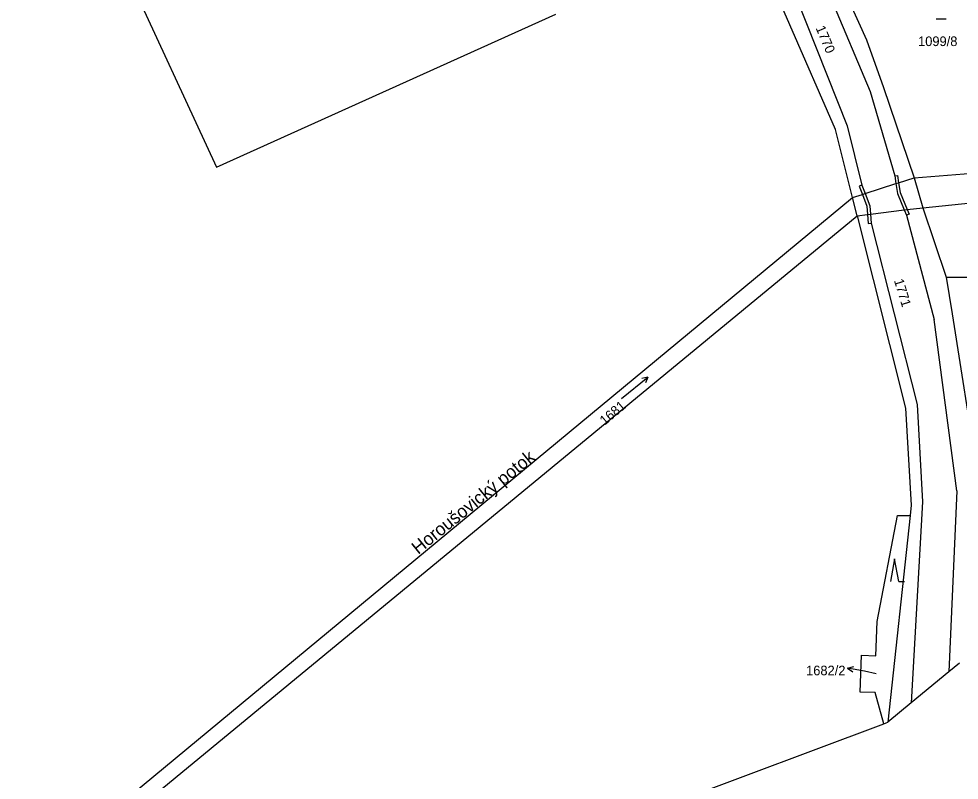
# Model space of a CAD drawing. Extents: x -724107 to -720612, y -1045267 to -1038441.
# Drawn here: x -722136.9 to -721970.9, y -1044488.4 to -1044354 of the extents above; entities that cross this region are included whole.
import ezdxf

# ---------------------------------------------------------------- set-up
doc = ezdxf.new("R2010")
doc.units = 0
for name, color, linetype in [('Hranice kat_území', 7, 'Continuous'), ('Hranice parcel', 7, 'Continuous'), ('Parcelní čísla', 7, 'Continuous'), ('Pop  PČ popisy', 7, 'Continuous'), ('Vnitřní kresba', 7, 'Continuous'), ('Značky kultur', 7, 'Continuous')]:
    doc.layers.add(name, color=color, linetype=linetype)

msp = doc.modelspace()

# ---------------------------------------------------------------- linework, layer by layer
at = {"layer": 'Hranice kat_území'}
for p, q in [((-722037.47, -1044498.36), (-721984.24, -1044478.41)), ((-721984.24, -1044478.41), (-721983.81, -1044478.25)), ((-721983.81, -1044478.25), (-721983.52, -1044478.14))]:
    msp.add_line(p, q, dxfattribs=at)
msp.add_lwpolyline([(-721970.87, -1044467.72), (-721972.74, -1044469.26), (-721979.36, -1044474.72), (-721983.52, -1044478.14)], dxfattribs=at)
at = {"layer": 'Hranice parcel'}
for p, q in [((-721978.83, -1044382.04), (-721952.21, -1044380)), ((-721978.83, -1044382.04), (-721977.33, -1044387.33)), ((-721977.33, -1044387.33), (-721924.74, -1044381.95)), ((-721988.93, -1044388.75), (-721989.74, -1044385.55)), ((-721977.33, -1044387.33), (-721973.2, -1044399.62)), ((-721973.2, -1044399.62), (-721957.88, -1044399.48)), ((-721979.56, -1044441.69), (-721983.52, -1044478.14))]:
    msp.add_line(p, q, dxfattribs=at)
for points in [[(-721998.33, -1044333.24), (-721987.3, -1044357.71), (-721984.26, -1044366.09), (-721978.83, -1044382.04)], [(-721989.74, -1044385.55), (-721992.77, -1044373.53), (-722008.86, -1044336.5)], [(-722104.47, -1044338.92), (-722118.13, -1044345.39), (-722102.03, -1044380.2), (-722042.11, -1044353.18)], [(-721989.74, -1044385.55), (-721988, -1044384.99), (-721987.53, -1044384.84), (-721982.07, -1044383.08), (-721981.6, -1044382.93), (-721978.83, -1044382.04)], [(-722053.27, -1045000.58), (-722053.77, -1044998.94), (-722074.32, -1044931.23), (-722227.92, -1044667.78), (-722226.93, -1044581.87), (-721989.74, -1044385.55)], [(-722071.05, -1044929.99), (-722224.9, -1044666.02), (-722223.43, -1044581.93), (-721988.93, -1044388.75)], [(-721988.93, -1044388.75), (-721980.37, -1044422.73), (-721979.36, -1044439.84), (-721979.56, -1044441.69)], [(-721973.2, -1044399.62), (-721972.16, -1044406.09), (-721967.74, -1044434.1)], [(-721984.24, -1044478.41), (-721985.75, -1044472.93), (-721988.39, -1044472.82), (-721988.14, -1044466.33), (-721985.64, -1044466.42), (-721985.41, -1044460.39), (-721981.82, -1044441.69), (-721979.56, -1044441.69)]]:
    msp.add_lwpolyline(points, dxfattribs=at)
at = {"layer": 'Pop  PČ popisy'}
for p, q in [((-721990.6, -1044468.6), (-721989.52, -1044468.3)), ((-721987.65, -1044469.17), (-721990.6, -1044468.6)), ((-721990.6, -1044468.6), (-721989.71, -1044469.28)), ((-721985.56, -1044469.59), (-721987.65, -1044469.17))]:
    msp.add_line(p, q, dxfattribs=at)
at = {"layer": 'Vnitřní kresba'}
for p, q in [((-722000.48, -1044333.91), (-721986.61, -1044366.83)), ((-722005.5, -1044335.5), (-721990.69, -1044372.87)), ((-721986.61, -1044366.83), (-721982.29, -1044381.73)), ((-721990.69, -1044372.87), (-721988.1, -1044383.38)), ((-721982.29, -1044381.73), (-721981.8, -1044381.65)), ((-721982.29, -1044381.73), (-721982.07, -1044383.08)), ((-721981.8, -1044381.65), (-721981.6, -1044382.93)), ((-721988.1, -1044383.38), (-721988.57, -1044383.56)), ((-721988.1, -1044383.38), (-721987.53, -1044384.84)), ((-721982.07, -1044383.08), (-721981.79, -1044384.83)), ((-721981.6, -1044382.93), (-721981.33, -1044384.64)), ((-721988.57, -1044383.56), (-721988, -1044384.99)), ((-721988, -1044384.99), (-721987.19, -1044387.04)), ((-721987.53, -1044384.84), (-721986.69, -1044387)), ((-721981.79, -1044384.83), (-721980.6, -1044387.73)), ((-721981.33, -1044384.64), (-721980.09, -1044387.67)), ((-721987.19, -1044387.04), (-721987.08, -1044388.52)), ((-721986.69, -1044387), (-721986.58, -1044388.46)), ((-721986.58, -1044388.46), (-721980.6, -1044387.73)), ((-721980.6, -1044387.73), (-721980.09, -1044387.67)), ((-721980.6, -1044387.73), (-721980.22, -1044388.66)), ((-721980.09, -1044387.67), (-721977.33, -1044387.33)), ((-721980.09, -1044387.67), (-721979.76, -1044388.47)), ((-721988.93, -1044388.75), (-721987.08, -1044388.52)), ((-721987.08, -1044388.52), (-721986.58, -1044388.46)), ((-721987.08, -1044388.52), (-721986.96, -1044390.13)), ((-721986.58, -1044388.46), (-721986.46, -1044390.09)), ((-721979.76, -1044388.47), (-721980.22, -1044388.66)), ((-721980.22, -1044388.66), (-721975.3, -1044407.08)), ((-721986.96, -1044390.13), (-721986.46, -1044390.09)), ((-721986.46, -1044390.09), (-721978.33, -1044422.08)), ((-721971.32, -1044437.32), (-721975.3, -1044407.08)), ((-721978.33, -1044422.08), (-721977.36, -1044439.23)), ((-721971.32, -1044437.32), (-721972.74, -1044469.26)), ((-721977.36, -1044439.23), (-721979.36, -1044474.72))]:
    msp.add_line(p, q, dxfattribs=at)
at = {"layer": 'Značky kultur'}
for p, q in [((-721974.96, -1044353.99), (-721973.21, -1044353.99)), ((-722030.52, -1044421.03), (-722025.86, -1044417.26)), ((-722025.86, -1044417.26), (-722026.94, -1044417.48)), ((-722025.86, -1044417.26), (-722026.3, -1044418.26)), ((-721982.3, -1044449.3), (-721983.05, -1044453.3)), ((-721981.55, -1044453.3), (-721982.3, -1044449.3)), ((-721981.55, -1044453.3), (-721980.55, -1044453.3))]:
    msp.add_line(p, q, dxfattribs=at)

# ---------------------------------------------------------------- texts
at = {"layer": 'Parcelní čísla'}
for s, rotation, p in [('1770', 293, (-721996.28, -1044355.61)), ('1771', 287, (-721982.44, -1044400.17)), ('1681', 40, (-722033.5, -1044425.82))]:
    msp.add_text(s, height=1.7, rotation=rotation, dxfattribs=at).set_placement(p)
for s, p in [('1099/8', (-721978.17, -1044358.8)), ('1682/2', (-721997.94, -1044469.87))]:
    msp.add_text(s, height=1.7, dxfattribs=at).set_placement(p)
at = {"layer": 'Pop  PČ popisy'}
msp.add_text('Horoušovický potok', height=2.3, rotation=39, dxfattribs=at).set_placement((-722066.43, -1044448.63))

doc.saveas('drawing.dxf')
